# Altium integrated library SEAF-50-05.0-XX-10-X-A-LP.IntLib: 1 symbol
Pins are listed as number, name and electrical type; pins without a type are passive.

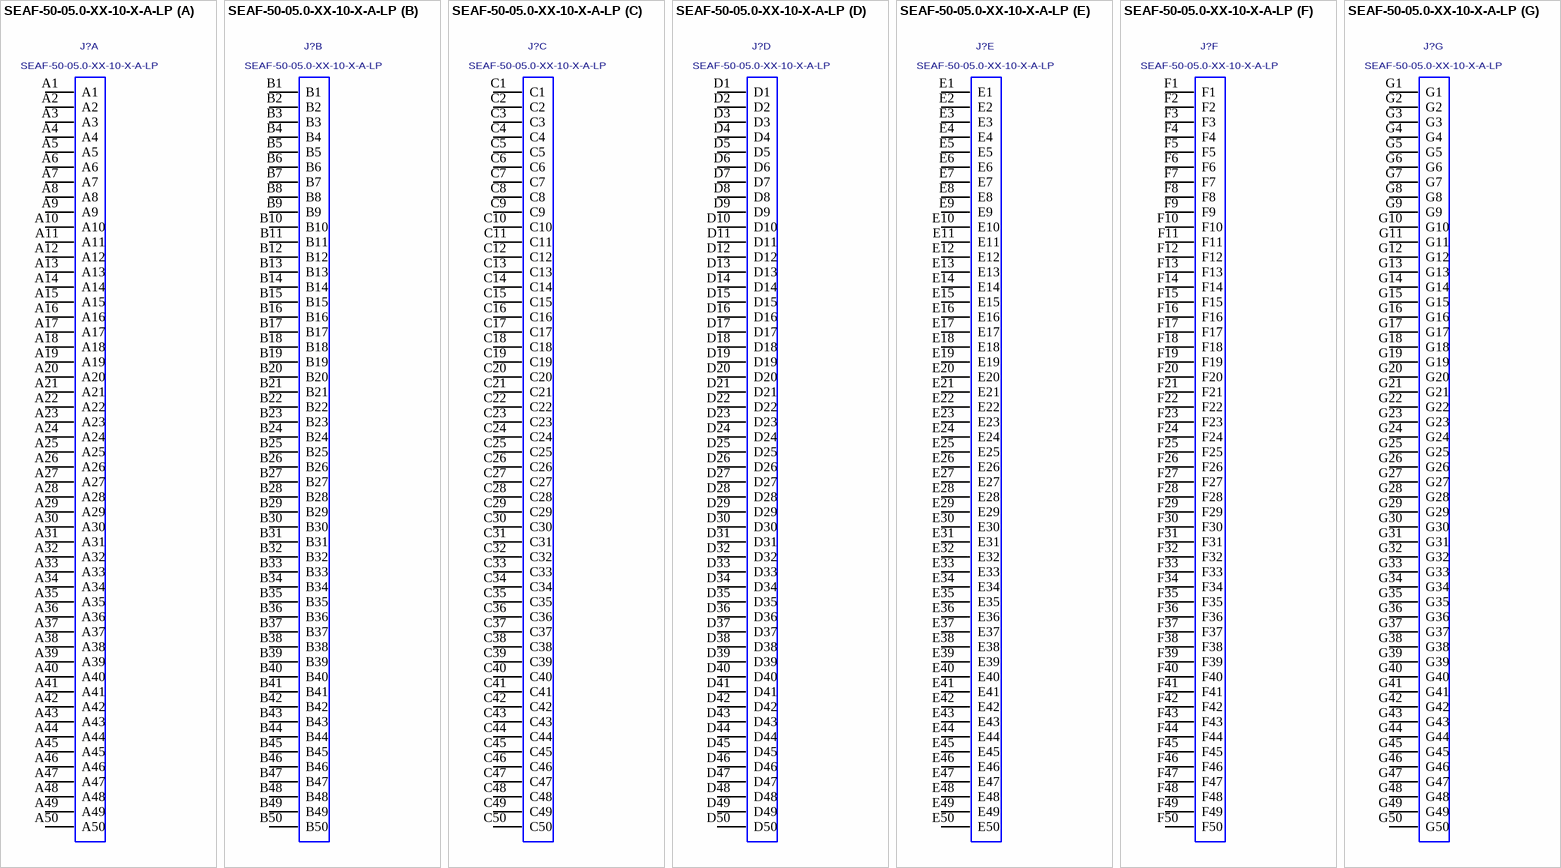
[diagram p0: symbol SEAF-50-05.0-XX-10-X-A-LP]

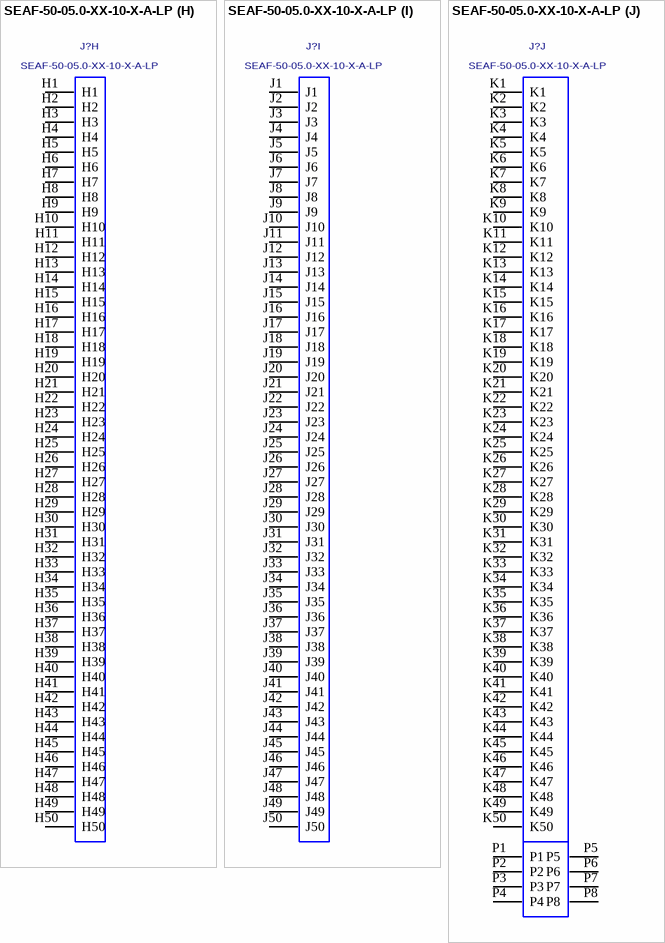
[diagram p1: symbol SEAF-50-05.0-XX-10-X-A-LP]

## SEAF-50-05.0-XX-10-X-A-LP
designator J?
Socket Array Assembly, Surface Mount With -LP Option, 0.050" Pitch, 500 Pins.; MANUFACTURER: SAMTEC
footprint SEAF-50-05.0-XX-10-X-A-LP
part A pins: A1, A2, A3, A4, A5, A6, A7, A8, A9, A10, A11, A12, A13, A14, A15, A16, A17, A18, A19, A20, A21, A22, A23, A24, A25, A26, A27, A28, A29, A30, A31, A32, A33, A34, A35, A36, A37, A38, A39, A40, A41, A42, A43, A44, A45, A46, A47, A48, A49, A50
part B pins: B1, B2, B3, B4, B5, B6, B7, B8, B9, B10, B11, B12, B13, B14, B15, B16, B17, B18, B19, B20, B21, B22, B23, B24, B25, B26, B27, B28, B29, B30, B31, B32, B33, B34, B35, B36, B37, B38, B39, B40, B41, B42, B43, B44, B45, B46, B47, B48, B49, B50
part C pins: C1, C2, C3, C4, C5, C6, C7, C8, C9, C10, C11, C12, C13, C14, C15, C16, C17, C18, C19, C20, C21, C22, C23, C24, C25, C26, C27, C28, C29, C30, C31, C32, C33, C34, C35, C36, C37, C38, C39, C40, C41, C42, C43, C44, C45, C46, C47, C48, C49, C50
part D pins: D1, D2, D3, D4, D5, D6, D7, D8, D9, D10, D11, D12, D13, D14, D15, D16, D17, D18, D19, D20, D21, D22, D23, D24, D25, D26, D27, D28, D29, D30, D31, D32, D33, D34, D35, D36, D37, D38, D39, D40, D41, D42, D43, D44, D45, D46, D47, D48, D49, D50
part E pins: E1, E2, E3, E4, E5, E6, E7, E8, E9, E10, E11, E12, E13, E14, E15, E16, E17, E18, E19, E20, E21, E22, E23, E24, E25, E26, E27, E28, E29, E30, E31, E32, E33, E34, E35, E36, E37, E38, E39, E40, E41, E42, E43, E44, E45, E46, E47, E48, E49, E50
part F pins: F1, F2, F3, F4, F5, F6, F7, F8, F9, F10, F11, F12, F13, F14, F15, F16, F17, F18, F19, F20, F21, F22, F23, F24, F25, F26, F27, F28, F29, F30, F31, F32, F33, F34, F35, F36, F37, F38, F39, F40, F41, F42, F43, F44, F45, F46, F47, F48, F49, F50
part G pins: G1, G2, G3, G4, G5, G6, G7, G8, G9, G10, G11, G12, G13, G14, G15, G16, G17, G18, G19, G20, G21, G22, G23, G24, G25, G26, G27, G28, G29, G30, G31, G32, G33, G34, G35, G36, G37, G38, G39, G40, G41, G42, G43, G44, G45, G46, G47, G48, G49, G50
part H pins: H1, H2, H3, H4, H5, H6, H7, H8, H9, H10, H11, H12, H13, H14, H15, H16, H17, H18, H19, H20, H21, H22, H23, H24, H25, H26, H27, H28, H29, H30, H31, H32, H33, H34, H35, H36, H37, H38, H39, H40, H41, H42, H43, H44, H45, H46, H47, H48, H49, H50
part I pins: J1, J2, J3, J4, J5, J6, J7, J8, J9, J10, J11, J12, J13, J14, J15, J16, J17, J18, J19, J20, J21, J22, J23, J24, J25, J26, J27, J28, J29, J30, J31, J32, J33, J34, J35, J36, J37, J38, J39, J40, J41, J42, J43, J44, J45, J46, J47, J48, J49, J50
part J pins: K1, K2, K3, K4, K5, K6, K7, K8, K9, K10, K11, K12, K13, K14, K15, K16, K17, K18, K19, K20, K21, K22, K23, K24, K25, K26, K27, K28, K29, K30, K31, K32, K33, K34, K35, K36, K37, K38, K39, K40, K41, K42, K43, K44, K45, K46, K47, K48, K49, K50, P1, P2, P3, P4, P5, P6, P7, P8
